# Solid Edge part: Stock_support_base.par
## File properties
Title: Stock Support Base
Author: Abhinav Rai
Template: Normal.par
Last saved by: TIET
Revision: 24
Application: Solid Edge
Accuracy: 0.99
Material: aluminum
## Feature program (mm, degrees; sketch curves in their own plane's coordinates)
sketch for "unnamed RevolvedProtrusion 1" plane through (0, 0, 0) normal (0, -1, 0) x-axis (1, 0, 0)
  line (0, 29.2468) -> (71.7103, 29.2468)
  line (71.7103, 29.2468) -> (71.7103, 19.7218)
  line (71.7103, 19.7218) -> (165.1, -256.5032)
  line (165.1, -256.5032) -> (215.9, -256.5032)
  line (215.9, -256.5032) -> (215.9, -281.9032)
  line (215.9, -281.9032) -> (156.9298, -281.9032)
  line (156.9298, -281.9032) -> (85.052, -69.3053)
  arc centre (73.021, -73.3729) radius 12.7 from (60.325, -73.0538) to (85.052, -69.3053) cw
  line (60.325, -73.0538) -> (57.15, -199.3532)
  line (57.15, -199.3532) -> (0, -199.3532)
  line (0, 29.2468) -> (0, -199.3532)
revolve "unnamed RevolvedProtrusion 1" add full turn 360 deg
sketch for "unnamed Hole 1" plane through (0, 0, 29.2468) normal (0, 0, 1) x-axis (1, 0, 0)
  hole centre (0, 0) bore radius 38.1
hole "unnamed Hole 1" through
sketch for "ExtrudedProtrusion_2" plane through (0, 0, -256.5032) normal (0, 0, 1) x-axis (0, 1, 0)
  arc centre (0, -119.2664) radius 41.0756 from (-18.7686, -155.8034) to (18.7686, -155.8034) ccw
  line (-18.7686, -197.1314) -> (-18.7686, -155.8034)
  arc centre (0, -197.1314) radius 18.7686 from (18.7686, -197.1314) to (-18.7686, -197.1314) cw
  line (18.7686, -197.1314) -> (18.7686, -155.8034)
extrude "ExtrudedProtrusion_2" add finite 12.7 along +normal
sketch for "unnamed Hole 2" plane through (187.8036, 0, -243.8032) normal (0, 0, 1) x-axis (1, 0, 0)
hole "unnamed Hole 2" through
fillet "Round_4" radius 3.175
pattern "unnamed Pattern 1" of "ExtrudedProtrusion_2", "unnamed Hole 2", "Round_4"
pattern "unnamed Pattern 2"
sketch for "ExtrudedProtrusion_3" plane through (0, -134.62, 0) normal (0, -1, 0) x-axis (1, 0, 0)
  circle centre (0, -2.5032) radius 19.05
extrude "ExtrudedProtrusion_3" add  Plane_Distance = 134.62 mm
adv blend "unnamed AdvBlend 1"
sketch for "ExtrudedProtrusion_4" plane through (0, -134.62, -2.5032) normal (0, -1, 0) x-axis (1, 0, 0)
  circle centre (0, -3.81) radius 22.225
extrude "ExtrudedProtrusion_4" add finite 9.525 along +normal
mirror "unnamed Mirror 1" of "ExtrudedProtrusion_4", "unnamed AdvBlend 1", "ExtrudedProtrusion_3" about plane through (0, 0, 0) normal (0, -1, 0)
extrude "unnamed Protrusion 1" add
adv blend "unnamed AdvBlend 2"
extrude "unnamed Protrusion 2" add finite 9.525
sketch for "ExtrudedProtrusion_7" plane through (104.775, 0, 0) normal (1, 0, 0) x-axis (0, 1, 0)
  circle centre (0, -167.6032) radius 19.05
extrude "ExtrudedProtrusion_7" add finite 41.275 along +normal  Plane_Distance = 104.775 mm
sketch for "Hole_6" plane through (146.05, 0, -167.6032) normal (1, 0, 0) x-axis (0, 1, 0)
  hole centre (0, 0) bore radius 7.9375
hole "Hole_6" diameter 15.875 finite
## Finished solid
Body 1: solid body, 55 faces, 97 edges, 41 vertices.
  Faces by surface: plane 26, cylinder 20, torus 4, cone 3, blend 2
  Edges by curve: circle 57, intersection 22, line 18
Bounding box of the edges (mm; curved faces can reach further): 431.800 x 431.800 x 311.150, from (-215.9, -215.9, -281.9032) to (215.9, 215.9, 29.2468).
Cylindrical faces by radius (mm): R7.9375 x2, R11.1125 x3, R15.875 x3, R18.7686 x3, R19.05 x4, R22.225 x2, R38.1 x1, R71.7103 x1, R215.9 x1
Conical faces (half-angle, radius in mm at the cone's reference point): 1.44 deg R60.325 x1, 18.68 deg R71.7103 x1, 18.68 deg R156.9298 x1
Toroidal faces (ring radius, tube radius in mm): R73.021 r12.7 x1, R163.0843 r3.175 x3
Planar faces by outward normal: +x 1, +y 4, +z 10, -x 1, -y 4, -z 2, oblique 4
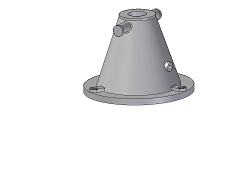
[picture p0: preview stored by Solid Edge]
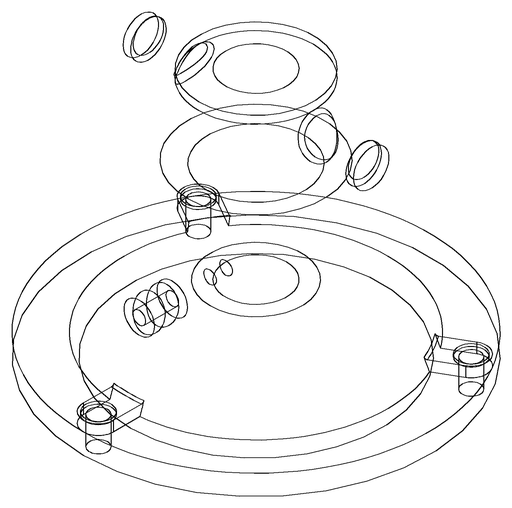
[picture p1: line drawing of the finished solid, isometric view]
